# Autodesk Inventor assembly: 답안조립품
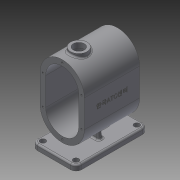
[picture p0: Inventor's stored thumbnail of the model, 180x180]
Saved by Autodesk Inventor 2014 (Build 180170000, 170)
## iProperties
Created: 2016-12
Part Number: 답안조립품
Document SubType Name: Assembly
Designer: user
Author: user
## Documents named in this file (2)
- C:\Users\user\Desktop\361208V1019\OldVersions\답안조립품.iam
- C:\Users\user\Desktop\361208V1019\본체.ipt
